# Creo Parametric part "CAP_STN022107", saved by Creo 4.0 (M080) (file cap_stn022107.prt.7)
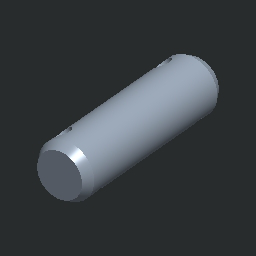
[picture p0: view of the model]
Units: millimeter Kilogram Sec (mmKs); MM, KILOGRAM, SECS
Materials in the file: OCEL

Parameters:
  MFG_WP_MATERIAL = "OCEL"
  NAZOV = "CAP_STN022107"
  NORMA = "STN 02 2107"
  PTC_MATERIAL_NAME = "OCEL"

Other parameters: HMOTNOST, HUSTOTA, D17, D2, D3

Created from: C022107.PRT

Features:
  1. datum plane "DTM2"

Layers: 1, 2, 3, 4, 5, 6, 7, 8, 9, 10, 11, 12, 13, 14, 15, 16, 17, 18, 19, 20, 21, 22, 23, 24, 25, 26, 27, 28, 29, 30, 31, 32

Family table entries: GENERIC, CAP_12X40, CAP_STN022107, value(d_val), 2/D, value(i_val), CAP_12X63, CAP_STN022107, !/(, CAP_12X95, CAP_STN022107, !/(, 2/U, CAP_12X110, CAP_STN022107, !/(, CAP_16X50, CAP_STN022107, !/0, 2/I, CAP_16X63, CAP_STN022107, !/0, CAP_16X80, CAP_STN022107, !/0, 2/T, CAP_20X63, CAP_STN022107, !/4, CAP_20X70, CAP_STN022107, !/4, CAP_20X85, CAP_STN022107, !/4, CAP_20X95, CAP_STN022107, !/4, 2/T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

Surfaces: 4 cone, 4 cylinder, 2 plane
